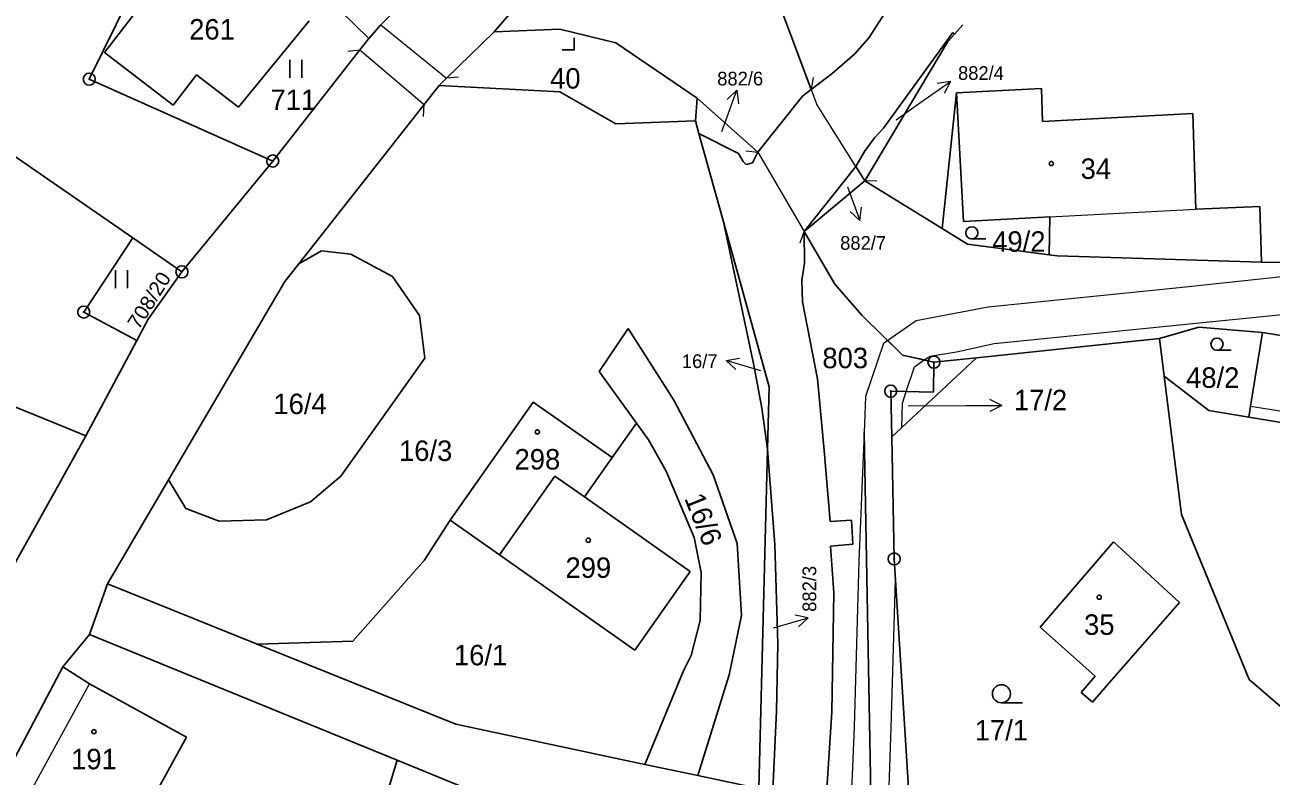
# Model space of a CAD drawing. Extents: x -739410 to -735662, y -942282 to -940043.
# Drawn here: x -738017.9 to -737914.5, y -941502 to -941439.7 of the extents above; entities that cross this region are included whole.
import ezdxf
from ezdxf.enums import TextEntityAlignment as Align

# ---------------------------------------------------------------- set-up
doc = ezdxf.new("R2010")
doc.units = 0
doc.header["$LTSCALE"] = 0.68
for name, color, linetype, lineweight in [('1', 7, 'Continuous', 25), ('13', 7, 'Continuous', 13), ('3', 7, 'Continuous', 25), ('4', 7, 'Continuous', 13), ('5', 7, 'Continuous', 25), ('7', 7, 'Continuous', 13), ('8', 7, 'Continuous', 25)]:
    doc.layers.add(name, color=color, linetype=linetype, lineweight=lineweight)
doc.layers.add('2', color=7, linetype='Continuous')

msp = doc.modelspace()

# ---------------------------------------------------------------- linework, layer by layer
at = {"layer": '1'}
for p, q in [((-738003.93, -941426.6), (-738012.59, -941444.17)), ((-738002.51, -941427.83), (-737989.39, -941440.81)), ((-737978.96, -941440.24), (-737968.51, -941428.15)), ((-737988.37, -941439.67), (-737979.18, -941430.22)), ((-738011.33, -941441.95), (-738003.74, -941432.09)), ((-737952.64, -941445.03), (-737956.44, -941434.86)), ((-737947.84, -941440.7), (-737945.38, -941436.88)), ((-737994.34, -941439.33), (-738000.19, -941446.49)), ((-737989.39, -941440.81), (-737988.37, -941439.67)), ((-737978.96, -941440.24), (-737982.93, -941444.1)), ((-737978.96, -941440.24), (-737973.51, -941440.03)), ((-737973.51, -941440.03), (-737968.86, -941441.15)), ((-737940.89, -941440.31), (-737946.65, -941448.24)), ((-737940.74, -941440.43), (-737940.89, -941440.31)), ((-737940.74, -941440.43), (-737940.04, -941439.66)), ((-737990.12, -941441.74), (-737989.39, -941440.81)), ((-737968.86, -941441.15), (-737962.1, -941445.75)), ((-737949.03, -941442.06), (-737947.84, -941440.7)), ((-737948.19, -941452.62), (-737941.3, -941441.04)), ((-737941.3, -941441.04), (-737940.74, -941440.43)), ((-738005.63, -941446.34), (-738011.33, -941441.95)), ((-737997.36, -941450.97), (-737990.12, -941441.74)), ((-737950.9, -941443.7), (-737949.03, -941442.06)), ((-738012.59, -941444.17), (-737997.36, -941450.97)), ((-738003.68, -941443.8), (-738005.63, -941446.34)), ((-738000.19, -941446.49), (-738003.68, -941443.8)), ((-737982.93, -941444.1), (-737983.53, -941444.69)), ((-737952.64, -941445.03), (-737950.9, -941443.7)), ((-737983.53, -941444.69), (-737984.78, -941446.28)), ((-737983.53, -941444.69), (-737973.51, -941445.23)), ((-737973.51, -941445.23), (-737968.86, -941447.88)), ((-737953.37, -941445.59), (-737952.64, -941445.03)), ((-737940.59, -941445.31), (-737941.78, -941456.56)), ((-737940.59, -941445.31), (-737933.52, -941444.94)), ((-737940.59, -941445.31), (-737939.99, -941455.99)), ((-737933.44, -941447.68), (-737933.52, -941444.94)), ((-737995.2, -941459.5), (-737984.78, -941446.28)), ((-737962.1, -941445.75), (-737962.25, -941447.63)), ((-737962.1, -941445.75), (-737957.08, -941450.23)), ((-737957.08, -941450.23), (-737953.37, -941445.59)), ((-737933.44, -941447.68), (-737920.95, -941447.02)), ((-737920.71, -941454.97), (-737920.95, -941447.02)), ((-737968.86, -941447.88), (-737962.25, -941447.63)), ((-737962.25, -941447.63), (-737961.96, -941448.68)), ((-737946.65, -941448.24), (-737947.38, -941449.04)), ((-737961.96, -941448.68), (-737959.93, -941456.02)), ((-737961.96, -941448.68), (-737958.67, -941450.35)), ((-737947.38, -941449.04), (-737948.22, -941450.18)), ((-738008.98, -941457.35), (-738018.99, -941450.42)), ((-737958.67, -941450.35), (-737958.3, -941451)), ((-737957.53, -941451.13), (-737957.08, -941450.23)), ((-737948.22, -941450.18), (-737948.93, -941451.43)), ((-738004.9, -941460.17), (-737997.36, -941450.97)), ((-737958.3, -941451), (-737958.04, -941451.25)), ((-737958.04, -941451.25), (-737957.53, -941451.13)), ((-737948.93, -941451.43), (-737953.23, -941456.81)), ((-737948.19, -941452.62), (-737948.93, -941451.43)), ((-737948.19, -941452.62), (-737953.23, -941456.81)), ((-737941.78, -941456.56), (-737948.19, -941452.62)), ((-737920.71, -941454.97), (-737915.4, -941454.75)), ((-737915.4, -941454.75), (-737915.24, -941459.36)), ((-737939.99, -941455.99), (-737932.83, -941455.61)), ((-737932.83, -941455.61), (-737932.88, -941458.75)), ((-737959.93, -941456.02), (-737956.14, -941469.72)), ((-737957.42, -941467.92), (-737959.93, -941456.02)), ((-737953.23, -941456.81), (-737950.67, -941461.2)), ((-737953.23, -941456.81), (-737953.19, -941459.46)), ((-737939.66, -941457.87), (-737941.78, -941456.56)), ((-738013.05, -941463.51), (-738008.98, -941457.35)), ((-738004.9, -941460.17), (-738008.98, -941457.35)), ((-737932.88, -941458.75), (-737939.66, -941457.87)), ((-737995.2, -941459.5), (-737993.31, -941458.43)), ((-737993.31, -941458.43), (-737990.86, -941458.7)), ((-737990.86, -941458.7), (-737987.4, -941460.56)), ((-737932.23, -941458.83), (-737932.88, -941458.75)), ((-737915.24, -941459.36), (-737932.23, -941458.83)), ((-737996.35, -941460.96), (-737995.2, -941459.5)), ((-737953.19, -941459.46), (-737953.42, -941460.87)), ((-737907.9, -941459.54), (-737915.24, -941459.36)), ((-738004.9, -941460.17), (-738007.71, -941464.11)), ((-737987.4, -941460.56), (-737985.17, -941463.8)), ((-737953.42, -941460.87), (-737953.37, -941462.67)), ((-737950.67, -941461.2), (-737948.43, -941463.78)), ((-737985.17, -941463.8), (-737984.73, -941467.35)), ((-737948.43, -941463.78), (-737945.05, -941467.09)), ((-737967.85, -941464.87), (-737970.25, -941468.44)), ((-737964.05, -941470.84), (-737967.85, -941464.87)), ((-737920.45, -941464.76), (-737923.73, -941465.7)), ((-737915.16, -941465.21), (-737920.45, -941464.76)), ((-738008.65, -941465.86), (-738012.89, -941473.8)), ((-737938.91, -941467.3), (-737923.73, -941465.7)), ((-737923.73, -941465.7), (-737923.33, -941468.84)), ((-737915.16, -941465.21), (-737916.17, -941471.32)), ((-737915.16, -941465.21), (-737901.29, -941467.48)), ((-737945.05, -941467.09), (-737942.45, -941467.67)), ((-738014.9, -941472.96), (-738026.65, -941468.18)), ((-737984.73, -941467.35), (-737991.69, -941477.15)), ((-737956.75, -941471.49), (-737957.42, -941467.92)), ((-737945.96, -941473.88), (-737938.91, -941467.3)), ((-737942.48, -941470.17), (-737942.45, -941467.67)), ((-737942.45, -941467.67), (-737938.91, -941467.3)), ((-737967.16, -941472.73), (-737970.25, -941468.44)), ((-737923.33, -941468.84), (-737921.89, -941480.32)), ((-737923.33, -941468.84), (-737919.63, -941471.69)), ((-737956.14, -941469.72), (-737956.27, -941474.89)), ((-737945.96, -941473.88), (-737946.04, -941470.08)), ((-737946.04, -941470.08), (-737942.48, -941470.17)), ((-737982.62, -941480.8), (-737975.72, -941470.98)), ((-737975.72, -941470.98), (-737969.17, -941475.58)), ((-737960.78, -941477.03), (-737964.05, -941470.84)), ((-737916.17, -941471.32), (-737916.29, -941472.24)), ((-737956.27, -941474.89), (-737956.75, -941471.49)), ((-737919.63, -941471.69), (-737916.29, -941472.24)), ((-737916.29, -941472.24), (-737911.86, -941472.97)), ((-738014.9, -941472.96), (-738012.89, -941473.8)), ((-737969.17, -941475.58), (-737967.16, -941472.73)), ((-737967.16, -941472.73), (-737966.16, -941474.11)), ((-738013.18, -941474.35), (-738020.96, -941488.3)), ((-738012.89, -941473.8), (-738013.18, -941474.35)), ((-737966.16, -941474.11), (-737964.68, -941476.72)), ((-737945.96, -941473.88), (-737945.75, -941484.01)), ((-737956.27, -941474.89), (-737956.99, -941503.08)), ((-737955.65, -941482.81), (-737956.27, -941474.89)), ((-737951.57, -941475), (-737951.06, -941480.91)), ((-737971.47, -941478.85), (-737969.17, -941475.58)), ((-738004.56, -941479.83), (-738006.01, -941477.44)), ((-737991.69, -941477.15), (-737994.22, -941479.27)), ((-737971.47, -941478.85), (-737973.93, -941477.13)), ((-737964.68, -941476.72), (-737962.36, -941482.22)), ((-737958.79, -941482.73), (-737960.78, -941477.03)), ((-737994.22, -941479.27), (-737997.88, -941480.77)), ((-737962.68, -941485.04), (-737971.47, -941478.85)), ((-738001.81, -941480.88), (-738004.56, -941479.83)), ((-737921.89, -941480.32), (-737916.28, -941494.03)), ((-737997.88, -941480.77), (-738001.81, -941480.88)), ((-737984.77, -941484.13), (-737982.62, -941480.8)), ((-737982.62, -941480.8), (-737978.53, -941483.67)), ((-737951.06, -941480.91), (-737949.3, -941480.8)), ((-737949.3, -941480.8), (-737949.18, -941482.78)), ((-737962.36, -941482.22), (-737961.78, -941485.14)), ((-737958.43, -941488.72), (-737958.79, -941482.73)), ((-737927.55, -941482.59), (-737933.63, -941489.68)), ((-737927.55, -941482.59), (-737922.05, -941487.63)), ((-737955.42, -941491.05), (-737955.65, -941482.81)), ((-737990.7, -941490.83), (-737984.77, -941484.13)), ((-737944.43, -941505.26), (-737945.75, -941484.01)), ((-737962.68, -941485.04), (-737967.28, -941491.58)), ((-737961.78, -941485.14), (-737961.86, -941489.13)), ((-738012.58, -941490.28), (-738011.07, -941486.09)), ((-737998.65, -941491.09), (-738011.07, -941486.09)), ((-737950.76, -941486.82), (-737950.94, -941496.7)), ((-737922.05, -941487.63), (-737928.07, -941494.49)), ((-737959.45, -941493.62), (-737958.43, -941488.72)), ((-737961.86, -941489.13), (-737962.6, -941492.03)), ((-737929.07, -941493.75), (-737933.63, -941489.68)), ((-738012.58, -941490.28), (-738014.78, -941492.97)), ((-738012.58, -941490.28), (-737987.03, -941500.71)), ((-737998.65, -941491.09), (-737990.7, -941490.83)), ((-737982.14, -941497.74), (-737998.65, -941491.09)), ((-737962.6, -941492.03), (-737963.28, -941493.35)), ((-737955.53, -941496.64), (-737955.42, -941491.05)), ((-738014.78, -941492.97), (-738019.6, -941502.11)), ((-738012.57, -941494.37), (-738014.78, -941492.97)), ((-737963.28, -941493.35), (-737966.45, -941501.07)), ((-737962.06, -941502), (-737959.45, -941493.62)), ((-737930.22, -941495.09), (-737929.07, -941493.75)), ((-737904.39, -941504.29), (-737916.28, -941494.03)), ((-738012.57, -941494.37), (-738004.51, -941498.81)), ((-737929.28, -941495.9), (-737930.22, -941495.09)), ((-737928.07, -941494.49), (-737929.28, -941495.9)), ((-737955.93, -941505.61), (-737955.53, -941496.64)), ((-737950.94, -941496.7), (-737951.7, -941508.41)), ((-737966.45, -941501.07), (-737982.14, -941497.74)), ((-738007.6, -941504.42), (-738004.51, -941498.81)), ((-737988.45, -941505.43), (-737987.03, -941500.71)), ((-737987.03, -941500.71), (-737980.87, -941503.23)), ((-737962.06, -941502), (-737966.45, -941501.07)), ((-737956.99, -941503.08), (-737962.06, -941502))]:
    msp.add_line(p, q, dxfattribs=at)
for points in [[(-738011.07, -941486.09), (-738006.01, -941477.44), (-737996.35, -941460.96)], [(-737953.37, -941462.67), (-737952.12, -941469.06), (-737951.57, -941475)], [(-738007.71, -941464.11), (-738008.65, -941465.86), (-738013.05, -941463.51)], [(-737973.93, -941477.13), (-737978.53, -941483.67), (-737967.28, -941491.58)], [(-737949.18, -941482.78), (-737951.03, -941482.96), (-737950.76, -941486.82)]]:
    msp.add_lwpolyline(points, dxfattribs=at)
at = {"layer": '13'}
msp.add_lwpolyline([(-737905.25, -941459.7), (-737922.09, -941461.51), (-737937.94, -941463.1), (-737943.94, -941464.24), (-737946.29, -941465.87), (-737945.05, -941467.09), (-737943.25, -941467.49), (-737942.76, -941467.16), (-737940.57, -941466.8), (-737937.46, -941466.12), (-737921.79, -941464.55), (-737904.72, -941462.84)], dxfattribs=at)
for points in [[(-737946.18, -941502.89), (-737946, -941498.04), (-737945.64, -941485.74), (-737945.75, -941484.01), (-737945.96, -941473.88), (-737945.13, -941473.11), (-737945.05, -941471.07), (-737944.75, -941470.11), (-737944.07, -941468.06), (-737943.25, -941467.49), (-737945.05, -941467.09), (-737946.29, -941465.87), (-737946.65, -941466.12), (-737948.13, -941470.51), (-737948.25, -941473.52), (-737947.7, -941503.53), (-737947.83, -941508.19), (-737950.02, -941522.24), (-737948.43, -941522.35), (-737948.09, -941517.32)], [(-737949.08, -941497.94), (-737949.26, -941502.63), (-737951.15, -941517.02), (-737951.48, -941521.84), (-737951.5, -941522.16), (-737950.97, -941522.19), (-737950.02, -941522.24), (-737947.83, -941508.19), (-737947.7, -941503.53), (-737948.25, -941473.52), (-737948.68, -941484.19)]]:
    msp.add_lwpolyline(points, close=True, dxfattribs=at)
at = {"layer": '3'}
for p, q in [((-737995.931, -941444.07), (-737995.931, -941442.57)), ((-737994.93, -941444.07), (-737994.93, -941442.57)), ((-737939.305, -941457.44), (-737938.133, -941457.44)), ((-738010.421, -941461.53), (-738010.421, -941460.03)), ((-738009.42, -941461.53), (-738009.42, -941460.03)), ((-737918.945, -941466.68), (-737917.773, -941466.68)), ((-737936.843, -941495.96), (-737935.093, -941495.96))]:
    msp.add_line(p, q, dxfattribs=at)
msp.add_lwpolyline([(-737973.321, -941441.75), (-737972.32, -941441.75), (-737972.32, -941440.75)], dxfattribs=at)
for centre, radius in [((-737939.3052, -941456.9374), 0.5025), ((-737918.9452, -941466.1774), 0.5025), ((-737936.8429, -941495.2098), 0.75)]:
    msp.add_circle(centre, radius, dxfattribs=at)
at = {"layer": '4'}
for p, q in [((-737988.37, -941439.67), (-737982.93, -941444.1)), ((-737991.113, -941441.861), (-737990.121, -941441.74)), ((-737990.12, -941441.74), (-737984.78, -941446.28)), ((-737981.935, -941443.996), (-737982.929, -941444.101)), ((-737952.466, -941444.045), (-737952.639, -941445.03)), ((-737952.64, -941445.03), (-737952.2, -941446.22)), ((-737984.85, -941447.278), (-737984.781, -941446.281)), ((-737948.93, -941451.43), (-737952.2, -941446.22)), ((-737958.075, -941450.125), (-737957.081, -941450.229)), ((-737957.08, -941450.23), (-737953.23, -941456.81)), ((-737947.19, -941452.638), (-737948.189, -941452.621)), ((-737932.83, -941455.61), (-737920.71, -941454.97)), ((-737953.556, -941457.756), (-737953.231, -941456.81)), ((-737916.17, -941471.32), (-737911.74, -941472.04)), ((-738017.46, -941503.34), (-738012.57, -941494.37))]:
    msp.add_line(p, q, dxfattribs=at)
at = {"layer": '5'}
for centre in [(-737932.7068, -941451.1792), (-737975.3868, -941473.4592), (-737971.1568, -941482.4592), (-737928.7268, -941487.1892), (-738012.2068, -941498.3492)]:
    msp.add_circle(centre, 0.175, dxfattribs=at)
at = {"layer": '7'}
for p, q in [((-737941.072, -941444.369), (-737942.179, -941444.533)), ((-737958.814, -941445.1), (-737959.627, -941445.87)), ((-737948.604, -941455.92), (-737948.476, -941454.808)), ((-737959.7, -941467.523), (-737958.889, -941468.294)), ((-737936.809, -941471.26), (-737937.81, -941470.759)), ((-737952.885, -941488.893), (-737953.986, -941488.688))]:
    msp.add_line(p, q, dxfattribs=at)
for points in [[(-737945.6, -941447.54), (-737943.53, -941446.09), (-737941.072, -941444.369), (-737941.605, -941445.353)], [(-737960.06, -941448.51), (-737959.84, -941447.92), (-737958.814, -941445.1), (-737958.686, -941446.212)], [(-737949.63, -941453.1), (-737948.604, -941455.92), (-737949.417, -941455.15)], [(-737956.83, -941468.4), (-737959.7, -941467.523), (-737958.596, -941467.337)], [(-737944.58, -941471.3), (-737939.81, -941471.26), (-737936.809, -941471.26), (-737937.81, -941471.761)], [(-737955.77, -941489.72), (-737952.885, -941488.893), (-737953.71, -941489.65)]]:
    msp.add_lwpolyline(points, dxfattribs=at)
at = {"layer": '8'}
for centre, radius in [((-738012.59, -941444.1699), 0.5), ((-738012.59, -941444.1699), 0.0303), ((-737997.36, -941450.9699), 0.5), ((-737997.36, -941450.9699), 0.0303), ((-738004.9, -941460.1699), 0.5), ((-738004.9, -941460.1699), 0.0303), ((-738013.05, -941463.5099), 0.5), ((-738013.05, -941463.5099), 0.0303), ((-737942.45, -941467.6699), 0.5), ((-737942.45, -941467.6699), 0.0303), ((-737946.04, -941470.0799), 0.5), ((-737946.04, -941470.0799), 0.0303), ((-737945.75, -941484.0099), 0.5), ((-737945.75, -941484.0099), 0.0303)]:
    msp.add_circle(centre, radius, dxfattribs=at)

# ---------------------------------------------------------------- texts
at = {"layer": '2'}
for s, height, p in [('261', 1.7, (-738002.399, -941440.885)), ('40', 1.7, (-737973.059, -941444.955)), ('882/6', 1.139, (-737958.54, -941444.694)), ('711', 1.7, (-737995.649, -941446.735)), ('34', 1.7, (-737929.009, -941452.455)), ('49/2', 1.7, (-737935.399, -941458.505)), ('882/7', 1.139, (-737948.33, -941458.338)), ('803', 1.7, (-737949.819, -941468.175)), ('48/2', 1.7, (-737919.299, -941469.805)), ('16/4', 1.7, (-737995.089, -941471.985)), ('16/3', 1.7, (-737984.659, -941475.875)), ('298', 1.7, (-737975.379, -941476.585)), ('299', 1.7, (-737971.149, -941485.585)), ('35', 1.7, (-737928.719, -941490.315)), ('16/1', 1.7, (-737980.099, -941492.845)), ('17/1', 1.7, (-737936.849, -941499.085)), ('191', 1.7, (-738012.199, -941501.475))]:
    msp.add_text(s, height=height, dxfattribs=at).set_placement(p, align=Align.CENTER)
for s, height, p in [('882/4', 1.139, (-737940.45, -941444.234)), ('17/2', 1.7, (-737935.81, -941471.665))]:
    msp.add_text(s, height=height, dxfattribs=at).set_placement(p)
at = {"layer": '2', "width": 1.05}
msp.add_text('708/20', height=1.2, rotation=58, dxfattribs=at).set_placement((-738007.1141, -941462.857), align=Align.CENTER)
at = {"layer": '2'}
msp.add_text('16/7', height=1.139, dxfattribs=at).set_placement((-737960.419, -941468.159), align=Align.RIGHT)
msp.add_text('16/6', height=1.7, rotation=292, dxfattribs=at).set_placement((-737962.3783, -941481.0211), align=Align.CENTER)
msp.add_text('882/3', height=1.139, rotation=90, dxfattribs=at).set_placement((-737952.22, -941488.4))

doc.saveas('drawing.dxf')
